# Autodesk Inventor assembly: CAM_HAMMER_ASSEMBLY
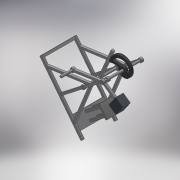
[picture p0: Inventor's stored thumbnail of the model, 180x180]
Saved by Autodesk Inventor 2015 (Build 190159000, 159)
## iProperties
Created: 2014-08
Part Number: CAM_HAMMER_ASSEMBLY
Document SubType Name: Assembly
Designer: lakshayg
Mass: 2872.86 g
Surface Area: 1276.17 cm^2
Volume: 365.969 cm^3
Density: 7.85 g/cm^3
Author: lakshayg
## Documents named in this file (15)
- C:\Users\Win 8.1\Desktop\CAM_HAMMER\ASSEMBLY\CAM_HAMMER_ASSEMBLY.iam
- C:\Users\Win 8.1\Desktop\CAM_HAMMER\PARTS\BASE_PART_1.ipt
- C:\Users\Win 8.1\Desktop\CAM_HAMMER\PARTS\BASE_PART_2.ipt
- C:\Users\Win 8.1\Desktop\CAM_HAMMER\PARTS\BASE_PART_3.ipt
- C:\Users\Win 8.1\Desktop\CAM_HAMMER\PARTS\VERTICAL_SUPPORT_1.ipt
- C:\Users\Win 8.1\Desktop\CAM_HAMMER\PARTS\VERTICAL_SUPPORT_2.ipt
- C:\Users\Win 8.1\Desktop\CAM_HAMMER\PARTS\AXLE_BEND.ipt
- C:\Users\Win 8.1\Desktop\CAM_HAMMER\PARTS\AXLE_CAM.ipt
- C:\Users\Win 8.1\Desktop\CAM_HAMMER\PARTS\HANDLE.ipt
- C:\Users\Win 8.1\Desktop\CAM_HAMMER\PARTS\HANDLE_AXLE.ipt
- C:\Users\Win 8.1\Desktop\CAM_HAMMER\PARTS\CAM.ipt
- C:\Users\Win 8.1\Desktop\CAM_HAMMER\PARTS\CAM_HAMMER_LINK_2.ipt
- C:\Users\Win 8.1\Desktop\CAM_HAMMER\PARTS\HAMMER.ipt
- C:\Users\Win 8.1\Desktop\CAM_HAMMER\PARTS\HAMMER_BASE.ipt
- C:\Users\Win 8.1\Desktop\CAM_HAMMER\PARTS\BASE_ROD.ipt
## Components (22 placed, 14 different names)
1. BASE_PART_1:1 — Mate:2, Flush:3, Mate:4, Flush:7, Mate:8, Mate:9, Mate:26, Flush:21, Symmetry:2
2. BASE_PART_1:2 — Mate:1, Flush:1, Mate:3, Flush:5, Flush:6, Mate:5, Mate:6, Mate:7, Flush:14, Flush:20, Flush:21, Symmetry:2
3. BASE_PART_2:1 — Mate:1, Flush:1, Mate:2, Flush:3, Angle:2, Mate:20, Mate:21, Mate:22, Mate:23, Flush:15, Flush:20
4. BASE_PART_3:1 — Mate:3, Flush:5, Flush:6
5. VERTICAL_SUPPORT_2:1 — Mate:5, Flush:8, Flush:9, Mate:10, Mate:13, Mate:19, Flush:14
6. VERTICAL_SUPPORT_2:2 — Insert:2, Mate:4, Flush:7, Flush:10, Flush:11, Insert:5, Mate:11, Mate:12
7. VERTICAL_SUPPORT_1:1 — Flush:11, Mate:9, Mate:11
8. VERTICAL_SUPPORT_1:2 — Flush:9, Mate:7, Mate:13
9. VERTICAL_SUPPORT_1:3 — Flush:8, Mate:6, Mate:10
10. VERTICAL_SUPPORT_1:4 — Flush:10, Mate:8, Mate:12, Mate:26
11. AXLE_BEND:1 — Insert:2, Mate:14, Mate:16, Mate:19
12. AXLE_CAM:1 — Insert:3, Insert:5, Mate:15, Angle:1, Rotation:1
13. HANDLE:1 — Insert:3, Insert:4, Angle:1
14. HANDLE_AXLE:1 — Insert:4
15. CAM:1 — Mate:15, Flush:12, Rotation:1
16. CAM_HAMMER_LINK_2:1 — Mate:14, Flush:12, Mate:16, Flush:13, Mate:17, Mate:18
17. HAMMER:1 — Flush:13, Mate:17, Mate:18
18. HAMMER_BASE:1 — Angle:2, Flush:15, Mate:24, Flush:22, Flush:23, Flush:24, Flush:25
19. BASE_ROD:1 — Mate:23, Mate:24, Flush:16, Flush:18
20. BASE_ROD:2 — Mate:22, Flush:16, Flush:17, Flush:25
21. BASE_ROD:3 — Mate:21, Flush:17, Flush:19, Flush:24, Symmetry:1
22. BASE_ROD:4 — Mate:20, Flush:18, Flush:19, Flush:22, Flush:23, Symmetry:1
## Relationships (57: Mate 25, Flush 23, Insert 4, Angle 2, Symmetry 2, RelateRotation 1)
- Mate:1: BASE_PART_1:2 ↔ BASE_PART_2:1
- Flush:1: BASE_PART_1:2 ↔ BASE_PART_2:1
- Mate:2: BASE_PART_1:1 ↔ BASE_PART_2:1
- Flush:3: BASE_PART_1:1 ↔ BASE_PART_2:1
- Mate:3: BASE_PART_1:2 ↔ BASE_PART_3:1
- Flush:5: BASE_PART_1:2 ↔ BASE_PART_3:1
- Flush:6: BASE_PART_1:2 ↔ BASE_PART_3:1
- Insert:2: VERTICAL_SUPPORT_2:2 ↔ AXLE_BEND:1
- Mate:4: BASE_PART_1:1 ↔ VERTICAL_SUPPORT_2:2
- Flush:7: BASE_PART_1:1 ↔ VERTICAL_SUPPORT_2:2
- Mate:5: BASE_PART_1:2 ↔ VERTICAL_SUPPORT_2:1
- Flush:8: VERTICAL_SUPPORT_2:1 ↔ VERTICAL_SUPPORT_1:3
- Flush:9: VERTICAL_SUPPORT_2:1 ↔ VERTICAL_SUPPORT_1:2
- Flush:10: VERTICAL_SUPPORT_2:2 ↔ VERTICAL_SUPPORT_1:4
- Flush:11: VERTICAL_SUPPORT_2:2 ↔ VERTICAL_SUPPORT_1:1
- Mate:6: BASE_PART_1:2 ↔ VERTICAL_SUPPORT_1:3
- Mate:7: BASE_PART_1:2 ↔ VERTICAL_SUPPORT_1:2
- Mate:8: BASE_PART_1:1 ↔ VERTICAL_SUPPORT_1:4
- Mate:9: BASE_PART_1:1 ↔ VERTICAL_SUPPORT_1:1
- Insert:3: AXLE_CAM:1 ↔ HANDLE:1
- Insert:4: HANDLE:1 ↔ HANDLE_AXLE:1
- Insert:5: VERTICAL_SUPPORT_2:2 ↔ AXLE_CAM:1
- Mate:10: VERTICAL_SUPPORT_2:1 ↔ VERTICAL_SUPPORT_1:3
- Mate:11: VERTICAL_SUPPORT_2:2 ↔ VERTICAL_SUPPORT_1:1
- Mate:12: VERTICAL_SUPPORT_2:2 ↔ VERTICAL_SUPPORT_1:4
- Mate:13: VERTICAL_SUPPORT_2:1 ↔ VERTICAL_SUPPORT_1:2
- Mate:14: AXLE_BEND:1 ↔ CAM_HAMMER_LINK_2:1
- Mate:15: AXLE_CAM:1 ↔ CAM:1
- Flush:12: CAM:1 ↔ CAM_HAMMER_LINK_2:1
- Mate:16: AXLE_BEND:1 ↔ CAM_HAMMER_LINK_2:1
- Angle:1: AXLE_CAM:1 ↔ HANDLE:1
- Rotation:1 [RelateRotation]: AXLE_CAM:1 ↔ CAM:1
- Flush:13: CAM_HAMMER_LINK_2:1 ↔ HAMMER:1
- Mate:17: CAM_HAMMER_LINK_2:1 ↔ HAMMER:1
- Mate:18: CAM_HAMMER_LINK_2:1 ↔ HAMMER:1
- Angle:2: BASE_PART_2:1 ↔ HAMMER_BASE:1
- Mate:19: VERTICAL_SUPPORT_2:1 ↔ AXLE_BEND:1
- Flush:14: BASE_PART_1:2 ↔ VERTICAL_SUPPORT_2:1
- Mate:20: BASE_PART_2:1 ↔ BASE_ROD:4
- Mate:21: BASE_PART_2:1 ↔ BASE_ROD:3
- Mate:22: BASE_PART_2:1 ↔ BASE_ROD:2
- Mate:23: BASE_PART_2:1 ↔ BASE_ROD:1
- Flush:15: BASE_PART_2:1 ↔ HAMMER_BASE:1
- Mate:24: HAMMER_BASE:1 ↔ BASE_ROD:1
- Flush:16: BASE_ROD:1 ↔ BASE_ROD:2
- Flush:17: BASE_ROD:2 ↔ BASE_ROD:3
- Flush:18: BASE_ROD:1 ↔ BASE_ROD:4
- Flush:19: BASE_ROD:3 ↔ BASE_ROD:4
- Mate:26: BASE_PART_1:1 ↔ VERTICAL_SUPPORT_1:4
- Flush:20: BASE_PART_1:2 ↔ BASE_PART_2:1
- Flush:21: BASE_PART_1:1 ↔ BASE_PART_1:2
- Flush:22: HAMMER_BASE:1 ↔ BASE_ROD:4
- Flush:23: HAMMER_BASE:1 ↔ BASE_ROD:4
- Flush:24: HAMMER_BASE:1 ↔ BASE_ROD:3
- Flush:25: HAMMER_BASE:1 ↔ BASE_ROD:2
- Symmetry:1: BASE_ROD:3 ↔ BASE_ROD:4
- Symmetry:2: BASE_PART_1:1 ↔ BASE_PART_1:2
